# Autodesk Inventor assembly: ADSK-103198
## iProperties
Shininess: 0.0
Created: 2001-01
Part Number: ADSK-103198
Document SubType Name: Assembly
Designer: gao
Stock Number: ADSK-103198
Density: 0.0
Volumn: 0.0
Area: 0.0
PropertySet Name: Model Information
Control State: 0
Master: False
Checked Out: False
Author: gao
